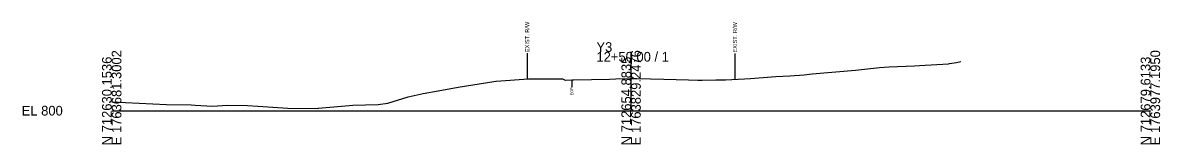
# Model space of a CAD drawing. Extents: x -26 to 2903, y -10 to 5022.
# Drawn here: x -25.7 to 302.8, y 2490.3 to 2525.4 of the extents above; entities that cross this region are included whole.
import ezdxf

# ---------------------------------------------------------------- set-up
doc = ezdxf.new("R2010")
doc.units = 0
for name, color, linetype in [('Default', 7, 'Continuous'), ('Exist Cross Section Cell', 7, 'Continuous'), ('Exist XS Ground Line', 7, 'Continuous'), ('Old_Level_10', 7, 'Continuous')]:
    doc.layers.add(name, color=color, linetype=linetype)

msp = doc.modelspace()

# ---------------------------------------------------------------- linework, layer by layer
at = {"layer": 'Exist Cross Section Cell'}
for p, q in [((150, 2500), (150, 2516.98)), ((0, 2500), (150, 2500)), ((150, 2500), (300, 2500))]:
    msp.add_line(p, q, dxfattribs=at)
at = {"layer": 'Exist XS Ground Line'}
msp.add_lwpolyline([(0, 2502.52), (15.84, 2501.83), (22.92, 2501.65), (24.12, 2501.62), (29.1, 2501.26), (33.48, 2501.64), (39.24, 2501.48), (42.17, 2501.27), (49.38, 2500.8), (50.86, 2500.77), (59.51, 2500.66), (59.54, 2500.66), (59.72, 2500.68), (69.65, 2501.61), (76.92, 2501.79), (79.79, 2502.16), (85.6, 2503.96), (89.93, 2504.97), (94.29, 2505.69), (100.07, 2506.79), (110.34, 2508.47), (110.92, 2508.54), (111.05, 2508.57), (120.35, 2509.21), (120.35, 2509.21), (130.18, 2509.24), (130.95, 2508.8), (130.97, 2508.79), (131.03, 2508.79), (132.89, 2508.88), (133.36, 2508.89), (143.81, 2509.1), (145.6, 2509.16), (150, 2509.26), (150.05, 2509.26), (151.65, 2509.25), (155.63, 2509.2), (159.51, 2509.08), (166.6, 2508.91), (169.25, 2508.85), (170.5, 2508.85), (174.45, 2508.89), (177.3, 2508.93), (179.09, 2509.04), (182.74, 2509.22), (184.5, 2509.29), (191.83, 2509.84), (195.83, 2510.11), (199.96, 2510.36), (202.3, 2510.61), (214.79, 2511.72), (221.73, 2512.44), (224.59, 2512.65), (231.87, 2512.96), (233.28, 2513.05), (241.69, 2513.57), (241.97, 2513.59), (242.01, 2513.59), (244, 2513.92), (245.28, 2514.22)], dxfattribs=at)
at = {"layer": 'Old_Level_10'}
for p, q in [((120, 2516.59), (120, 2509.19)), ((180, 2516.49), (180, 2509.08)), ((132.89, 2508.88), (132.89, 2506.83))]:
    msp.add_line(p, q, dxfattribs=at)

# ---------------------------------------------------------------- texts
at = {"layer": 'Default'}
msp.add_text('-', height=0.0001, dxfattribs=at).set_placement((0, 2500))
at = {"layer": 'Exist Cross Section Cell'}
for s, p in [('E 1763681.3002', (2.8, 2490)), ('E 1763829.2476', (152.8, 2490)), ('E 1763977.1950', (302.8, 2490)), ('N 712630.1536', (0, 2490)), ('N 712654.8835', (150, 2490)), ('N 712679.6133', (300, 2490))]:
    msp.add_text(s, height=2.8, rotation=90, dxfattribs=at).set_placement(p)
for s, p in [('Y3', (140, 2516.98)), ('12+50.00 / 1', (140, 2514.18)), ('EL 800', (-26, 2498.6))]:
    msp.add_text(s, height=2.8, dxfattribs=at).set_placement(p)
at = {"layer": 'Old_Level_10'}
for s, height, p in [('EXIST. R/W', 1.181, (120.59, 2516.89)), ('EXIST. R/W', 1.181, (180.59, 2516.79)), ('EOP', 0.787, (133.28, 2504.43))]:
    msp.add_text(s, height=height, rotation=90, dxfattribs=at).set_placement(p)

doc.saveas('drawing.dxf')
